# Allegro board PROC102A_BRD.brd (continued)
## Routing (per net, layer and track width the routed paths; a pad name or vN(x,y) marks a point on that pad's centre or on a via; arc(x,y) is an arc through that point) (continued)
N171944000: length 1.5
  BOTTOM w0.152: R91.1 103.4,88.17 Q9.2
N171947950: length 1.5
  BOTTOM w0.152: R96.1 103.4,138.59 Q10.2
N171966200: length 1.5
  BOTTOM w0.152: Q11.2 103.4,113.06 R97.1

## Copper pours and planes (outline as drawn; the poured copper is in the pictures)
5VOP on TOP: 108.27,28.57 108.27,24.7 111.36,24.7 111.36,28.57
5VOP on BOTTOM: 100.02,29.26 100.02,20.22 103.71,20.22 103.71,25.74 111.26,25.74 111.26,29.26
DGND on TOP: 23.64,1.03 23.64,25.48 8.14,25.48 8.14,152.56 150.28,152.56 151.29,152.56 151.29,26.42 151.3,26.42 151.3,25.46 135.76,25.46 135.76,9.82 135.05,9.11 135.05,9.29 128.7,2.93 97.78,2.93 97.78,1.03 ; 48 cut-outs
DGND on TOP: 71.12,125.05 71.12,119.82 66,119.82 66,125.05
DGND on TOP: 105.68,28.77 105.68,32.71 100.97,32.71 100.97,28.77
DGND on TOP: 70.23,127.76 70.23,134.61 65.88,134.61 65.88,127.76
DGND on TOP: 71.02,112.31 71.02,117.58 65.9,117.58 65.9,112.31
DGND on L02_GND1: 23.62,1.02 23.63,25.47 8.13,25.47 8.13,152.57 151.29,152.57 151.3,128.96 151.3,25.88 151.3,25.46 135.76,25.46 135.76,9.82 134.87,8.93 134.87,9.05 128.9,3.08 97.86,3.08 97.71,2.93 97.71,1.02
DGND on L05_GND2: 23.71,1.02 23.71,25.47 8.13,25.47 8.13,152.57 151.29,152.57 151.3,128.96 151.3,25.78 151.3,25.46 135.76,25.46 135.76,9.82 135.05,9.11 135.05,9.36 128.73,3.03 97.66,3.03 97.64,3.01 97.64,1.02
VCC1V8_HSE on BOTTOM: 70.08,1.81 83.33,1.81 83.33,3.34 78.49,3.34 78.49,4.3 71.47,4.3 71.47,4.53 66.7,4.53 66.7,3.52 70.08,3.52
VCC1V8_HSE on L04_PWR: 80.39,2.75 80.39,16 91.23,16 91.23,38.31 67,38.31 67,87.42 77.18,87.42 77.6,87 77.6,85.34 75.69,83.44 74.99,83.44 74.99,44.77 82.31,44.77 82.31,45.56 96.3,45.56 96.3,13.15 85.56,13.15 85.56,2.75
VCC3V3_IO_HSE on TOP: 86.58,129.98 86.58,126.14 84.52,126.14 84.52,124.55 84.02,124.55 84.02,129.98
VCC3V3_IO_HSE on TOP: 29.31,5.08 29.31,1.08 36.22,1.08 36.22,2.25 30.87,2.25 30.87,5.08
VCC3V3_IO_HSE on L04_PWR: 23.62,1.02 23.63,25.47 8.13,25.47 8.13,152.57 151.29,152.57 151.3,128.96 151.3,25.88 151.3,25.46 135.76,25.46 135.76,11.68 135.36,11.68 135.36,11 135.78,11 135.78,9.96 128.82,3 97.79,3 97.72,2.93 97.72,1.02 ; 6 cut-outs
VCC_5V0_HSE on TOP: 76.54,1.04 76.54,1.93 67.09,1.93 67.09,1.04
VCC_5V0_HSE on L04_PWR: 72.49,2.25 72.49,1.03 93.54,1.03 93.54,8.82 101.87,8.82 101.87,25.08 111.89,25.08 111.89,31.32 103.51,31.32 103.51,49.66 102.73,50.43 89.56,50.43 89.56,87.93 80.66,87.93 80.66,75.33 80.84,75.33 80.84,46.14 96.56,46.14 96.56,11.77 86.77,11.77 86.77,2.25
VCC_24V0 on BOTTOM (solid shape): 117.58,139.34 112.25,139.34 112.25,140.1 111.72,140.1 111.72,140.2 110.7,140.2 110.7,140.49 111.72,140.49 111.72,140.52 111.76,140.52 112.1,140.85 117.58,140.85
VCC_24V0 on BOTTOM (solid shape): 117.58,113.81 112.25,113.81 112.25,114.57 111.72,114.57 111.72,114.68 110.7,114.68 110.7,114.97 111.72,114.97 111.72,114.99 111.76,114.99 111.99,115.22 117.58,115.22
VCC_24V0 on BOTTOM (solid shape): 117.58,63.01 112.25,63.01 112.25,63.77 111.72,63.77 111.72,63.88 110.7,63.88 110.7,64.17 111.72,64.17 111.72,64.19 111.76,64.19 111.99,64.42 117.58,64.42
VCC_24V0 on BOTTOM (solid shape): 142.85,114.2 137.52,114.2 137.52,114.95 136.99,114.95 136.99,115.06 135.97,115.06 135.97,115.35 136.99,115.35 136.99,115.37 137.04,115.37 137.26,115.6 142.85,115.6
VCC_24V0 on BOTTOM (solid shape): 142.85,88.8 137.52,88.8 137.52,89.55 136.99,89.55 136.99,89.66 135.97,89.66 135.97,89.95 136.99,89.95 136.99,89.97 137.04,89.97 137.31,90.24 142.85,90.24
VCC_24V0 on BOTTOM (solid shape): 142.96,139.65 137.63,139.65 137.63,140.41 137.11,140.41 137.11,140.52 136.09,140.52 136.09,140.8 137.11,140.8 137.11,140.83 137.15,140.83 137.38,141.06 142.96,141.06
VCC_24V0 on BOTTOM (solid shape): 142.98,63.01 137.65,63.01 137.65,63.77 137.12,63.77 137.12,63.88 136.1,63.88 136.1,64.17 137.12,64.17 137.12,64.19 137.16,64.19 137.39,64.42 142.98,64.42
VCC_24V0 on BOTTOM (solid shape): 117.58,88.92 112.25,88.92 112.25,89.68 111.72,89.68 111.72,89.78 110.7,89.78 110.7,90.07 111.72,90.07 111.72,90.1 111.76,90.1 112.1,90.44 114.81,90.44 114.86,90.44 114.91,90.46 117.58,90.46
VCC_24V0 on TOP: 85.87,104.41 83.55,104.41 83.55,107.59 71.42,107.59 71.42,104.46 68.91,104.46 68.91,113.71 73,113.71 73,114.89 72.99,114.89 72.99,126.59 80.66,126.59 80.66,122.54 85.87,122.54 85.87,122.56 92.44,122.56 92.44,145.66 143.87,145.66 143.87,143.89 94.62,143.89 94.62,119.89 85.87,119.89
VCC_24V0 on TOP: 123.87,29.1 123.87,31.75 121.16,31.75 121.16,29.1
VCC_24V0 on L03_SIG1: 140.97,66 140.97,62.36 140.97,62.36 140.97,33.78 120.86,33.78 120.86,27.81 144.4,27.81 144.4,66
VCC_24V0 on L03_SIG1: 116.21,139.06 124.84,139.06 124.84,143 140.08,143 140.08,139.19 143.89,139.19 143.89,147.2 116.21,147.2
VCC_24V0 on L04_PWR: 120.52,32 125.73,32 125.73,14.66 127.39,13 135.64,13 135.64,9.88 132.86,7.11 125.1,7.11 120.52,11.68
(no net) on BOTTOM: 112.25,63.01 112.25,63.77 110.67,63.77 110.67,64.42 117.58,64.42 117.58,63.01
(no net) on BOTTOM: 112.25,113.81 112.25,114.57 110.67,114.57 110.67,115.22 117.58,115.22 117.58,113.81
(no net) on BOTTOM: 137.52,114.2 137.52,114.95 135.94,114.95 135.94,115.6 142.85,115.6 142.85,114.2
(no net) on BOTTOM: 112.25,88.92 112.25,89.68 110.67,89.68 110.67,90.46 117.58,90.46 117.58,88.92
(no net) on BOTTOM: 137.52,88.8 137.52,89.55 135.94,89.55 135.94,90.24 142.85,90.24 142.85,88.8
(no net) on BOTTOM: 112.25,139.34 112.25,140.1 110.67,140.1 110.67,140.85 117.58,140.85 117.58,139.34
(no net) on BOTTOM: 137.63,139.65 137.63,140.41 136.06,140.41 136.06,141.06 142.96,141.06 142.96,139.65
(no net) on BOTTOM: 137.65,63.01 137.65,63.77 136.07,63.77 136.07,64.42 142.98,64.42 142.98,63.01
(no net) on BOTTOM: 23.64,1.03 23.64,25.48 8.14,25.48 8.14,152.56 150.28,152.56 151.29,152.56 151.29,25.47 135.75,25.47 135.75,9.93 128.75,2.93 97.78,2.93 97.78,1.03 ; 61 cut-outs
(no net) on L03_SIG1: 23.62,1.02 23.63,25.47 8.13,25.47 8.13,152.57 151.29,152.57 151.3,128.96 151.3,25.83 151.3,25.46 135.76,25.46 135.76,9.82 135.1,9.16 135.1,9.28 128.9,3.08 97.82,3.08 97.79,3.05 97.79,1.14 97.66,1.02 ; 58 cut-outs
INPUT_24V0 on TOP: 70.97,139.57 70.97,127.9 80.55,127.9 80.55,139.57
L+_1 on TOP: 72.31,104.5 72.31,106.09 72.08,106.09 72.08,111.57 73.51,111.57 73.51,107.92 73.36,107.92 73.36,104.5
L+_1 on L04_PWR: 73.33,107.86 70.85,107.86 70.85,144.7 128.91,144.7 128.91,133.46 133.99,133.46 133.99,129.83 124.51,129.83 124.51,140.79 73.33,140.79
L+_2 on TOP: 73.56,104.5 73.56,106.23 79.76,106.23 79.76,104.5
L+_2 on L04_PWR: 77.92,106.47 77.92,104.54 80.77,104.54 80.77,120.52 121.69,120.52 121.69,105.28 134.09,105.28 134.09,109.73 127.26,109.73 127.26,125.1 78.74,125.1 78.74,106.47
L+_3 on TOP: 68.1,104.5 68.1,106.96 68.09,106.96 68.09,107.96 64.22,107.96 64.22,106.71 67.05,106.71 67.05,104.5
L+_3 on L04_PWR: 63.87,106.63 63.87,108.36 69.18,108.36 70.55,107 73.45,107 77.09,103.36 77.09,96.77 93.96,96.77 98.5,92.24 98.5,76.58 130.36,76.58 130.36,82.6 134.56,82.6 134.56,73.41 95.96,73.41 95.96,91.72 93.07,94.62 76.84,94.62 75.06,96.39 75.06,103.12 73.61,104.57 68.91,104.57 66.85,106.63
L+_4 on TOP: 66.85,104.5 66.85,106.07 63.3,106.07 63.3,104.5
L+_4 on L04_PWR: 62.95,106.11 62.95,93.01 66.93,89.03 90.68,89.03 90.68,52.38 102.03,52.38 105.52,48.89 135.09,48.89 135.09,57.78 130.84,57.78 130.84,51.9 106.85,51.9 104.02,54.74 93.03,54.74 93.03,90.74 92.04,91.73 68.8,91.73 65.53,95 65.53,106.11
L+_5 on TOP: 86.89,104.5 86.89,106.96 86.89,106.96 86.89,110.62 90.73,110.62 90.73,107.28 87.93,107.28 87.93,104.5
L+_5 on L04_PWR: 86.54,110.52 86.54,108.46 96.9,108.46 107.38,97.98 132.65,97.98 140.97,89.66 140.97,70.06 113.16,70.06 113.16,57.61 106.05,57.61 106.05,55.63 108.17,53.5 117.76,53.5 117.76,66.35 145.16,66.35 145.16,92.2 136.02,101.35 107.32,101.35 98.15,110.52
L+_6 on TOP: 88.13,104.5 88.13,106.5 94.36,106.5 94.36,101.41 91.74,101.41 91.74,104.5
L+_6 on L04_PWR: 91.63,103.44 91.63,101.09 94.87,101.09 101.47,94.49 101.47,79.5 108.64,79.5 108.64,83.14 104.25,83.14 104.25,95.87 96.68,103.44
L+_7 on TOP: 82.67,104.5 82.67,106.96 82.66,106.96 82.66,111.91 81.49,111.91 81.49,106.36 81.86,106.36 81.86,104.5
L+_7 on L04_PWR: 81.61,106.38 81.61,120.02 115.95,120.02 115.95,104.64 107.71,104.64 106.3,106.05 106.3,107.82 113.31,107.82 113.31,115.44 83.82,115.44 83.82,106.38
L+_8 on TOP: 81.42,104.5 81.42,105.95 81.03,105.95 81.03,109.86 76.07,109.86 76.07,106.93 80.12,106.93 80.12,104.5
L+_8 on L04_PWR: 76.09,107.58 78.06,107.58 78.06,130.64 108.84,130.64 108.84,134.09 76.09,134.09
N16732073 on TOP: 115.26,24.59 115.26,28.14 123.26,28.14 123.26,24.59
N16811368 on TOP: 91.63,134.04 91.63,143.35 82.32,143.35 82.32,134.04

Small or netless copper shapes (teardrops, artwork), in the pictures only: 259 on TOP, 313 on BOTTOM, 168 on L03_SIG1

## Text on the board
Ref Des/Assembly Bottom: PROC102A  ASSEMBLY BOTTOM
User.Comments: 5 | 6 | B1 | 2 | A14 | A2 | B2 | 4 | A10 | B10 | 11 | 8 | A12 | B12 | 12 | 16 | 30 | 37 | A32 | B32 | 24 | 25 | 36 | A31 | 9 | 10 | 13 | 18 | 19 | 20 | C | B | A | E | D | 3 | 7 | 15 | 32 | 33 | 31 | 64 | 65 | 96 | 40 | 23 | A11 | B11 | B14 | 48 | 128 | 21 | 97 | R170 | FSI | J23 | J24 | R8 | LD10 | J7 | C1 | J10 | R2 | TP28 | CPSW PHY | R3 | L7 | C23 | C143 | MCAN1 | R99 | LD25 | FB1 | TP5 | J14 | R153 | C122 | U32 | C2 | FB2 | R4 | R5 | C24 | MCAN0 | U36 | J27 | J9 | J31 | J21 | C28 | LD1 | R110 | R102 | C73 | C80 | C76 | C39 | C38 | C43 | R70 | TP11 | U9 | TP9 | C139 | C114 | R151 | C106 | TP19 | TP39 | R30 | U15 | C14 | FL7 | TP16 | C101 | C99 | C90 | C147 | TP17 | C205 | TP6 | U34 | C16 | R135 | C184 | R126 | R128 | L1 | C110 | C104 | R23 | TP56 | R52 | R56 | LD17 | C78 | C83 | C44 | C41 | U27 | U49 | R107 | R108 | R16 | TP96 | C89 | R51 | R54 | TP31 | C26 | J30 | J2 | R201 | R53 | R45 | R40 | U8 | HSE | C34 | C161 | J25 | RA2 | RA1 | U51 | TP43 | TP40 | C181 | R150 | R50 | R55 | R185 | TP20 | R19 | C100 | C102 | R93 | R98 | C168 | R189 | TP21 | C144 | R72 | R68 | TP7 | R177 | RA4 | R29 | C169 | R190 | C15 | U37 | R22 | R46 | BOOTMODE 0-7 | C121 | J8 | SW2 | C155 | C162 | U46 | R167 | U1 | R148 | U13 | R176 | R168 | TP4 | C476 | U23 | C145 | C146 | R157 | TP30 | U45 | R138 | R137 | TP15 | C133 | L2 | U48 | TP42 | C9 | R38 | C64 | R69 | R71 | R77 | SW3 | VDD CORE | U40 | C4 | U60 | GND | C134 | JTAG MUX SEL | Y1 | R140 | C27 | BOOTMODE 8-15 | R156 | R158 | R173 | R169 | R172 | C148 | C86 | J5 | TP54 | R174 | TP55 | C79 | C477 | C479 | I2C0 | U39 | J3 | SW4 | C113 | MCU PORz | ADC | VDDR CORE | C173 | R15 | U57 | R106 | R78 | C22 | C7 | R73 | SW5 | C45 | MCU RST | J20 | TP46 | TP23 | SOC WARM RST | R43 | U50 | U44 | TP70 | TP29 | C30 | R574 | U10 | C47 | R24 | R13 | J22 | J13 | C117 | SW6 | R191 | R92 | C72 | C486 | C77 | R12 | R192 | R186 | LD7 | C50 | C189 | U56 | TP24 | I2C1 | C171 | U33 | J4 | J19 | SW7 | J1 | R583 | R116 | R122 | LD20 | R143 | C57 | C54 | C174 | C176 | R82 | C151 | U11 | LD22 | R113 | R119 | TP32 | LD4 | C40 | C46 | U17 | U6 | L6 | C10 | C84 | C66 | C65 | R142 | TP12 | C167 | TP8 | R28 | J11 | C123 | L3 | U21 | U59 | R206 | TP2 | R207 | C31 | R20 | C33 | TP34 | R208 | D4 | C107 | C37 | TP38 | MCU RSTSTATz | LD15 | LD2 | U30 | C177 | C108 | 12V IN | C198 | U43 | LD5 | R204 | F1 | C56 | TP1 | D5 | R64 | J6 | R198 | R199 | C197 | R200 | U22 | C195 | C69 | OFF | C152 | C154 | U42 | Y2 | D6 | R7 | U58 | R134 | ON | FB8 | U61 | LD9 | C71 | D1 | C125 | D3 | R109 | R112 | TP18 | UART | TP81 | SW1 | JTAG | J28 | J26 | R80 | Q7 | Q4 | U19 | U31 | Q3 | U18 | U2 | U47 | U7 | U29 | U35 | Q1 | Q10 | Q8 | U41 | Q5 | Q2 | C153 | C29 | U3 | R136 | C3 | J32 | R9 | U4 | C140 | TP99 | C127 | C128 | C8 | C25 | ICSSG PHY | R76 | R37 | C141 | C111 | C67 | R564 | R565 | R94 | C112 | R96 | R97 | R95 | FB9 | C124 | R31 | R114 | R32 | LD11 | R115 | LD16 | R33 | R100 | R35 | U20 | R120 | R81 | R34 | R36 | R101 | R79 | C52 | R105 | LD12 | R42 | C51 | R104 | C36 | LD13 | C35 | R103 | C105 | LD18 | R41 | C68 | LD14 | R39 | LD19 | R121 | LD24 | LATCH IN1 | R59 | J15 | R60 | SYNC OUT2 | R61 | R21 | J16 | R65 | LATCH IN0 | J17 | SYNC OUT0 | TP22 | J18 | R187 | TP41 | RA3 | C58 | R83 | C18 | R194 | R84 | C91 | R85 | C182 | C92 | C59 | R86 | C93 | C19 | R188 | C11 | C60 | R87 | C12 | C61 | R88 | C53 | R195 | C13 | C62 | R89 | C183 | R90 | TP48 | C63 | R91 | R66 | R67 | C17 | R1 | C42 | R147 | R11 | C120 | R10 | FB6 | TP47 | LD26 | C156 | SOC/MCU GPIO | C163 | MCU WARM RST | U5 | R155 | SOC POR RST | R62 | C190 | R154 | R210 | R63 | R600 | C20 | R152 | R197 | C164 | R139 | C21 | C157 | R25 | LD23 | C165 | R178 | R179 | C75 | C387 | R180 | C98 | C194 | C103 | C74 | R181 | TP68 | RSTSTATz | J29 | FB5 | TP82 | R183 | FB3 | C97 | C87 | PORz OUT | R184 | R75 | R17 | R26 | R159 | R18 | R27 | R196 | C170 | R160 | R297 | R161 | R162 | TP61 | TP63 | R163 | SYNC1 OUT | C482 | C150 | C179 | R164 | R193 | U103 | C149 | J12 | LD3 | R124 | R165 | R132 | R166 | R125 | C483 | TP33 | R133 | C484 | L4 | TP14 | R575 | C495 | TP25 | TP27 | C485 | R14 | U14 | R74 | R144 | C95 | C178 | R145 | R127 | C494 | U102 | R123 | R175 | U25 | C129 | U16 | C109 | R47 | R117 | R584 | LD21 | R118 | R48 | TP51 | SAFETY | C96 | C126 | TP52 | C32 | R579 | C55 | C188 | U55 | LD8 | U28 | C5 | R602 | C70 | C180 | C6 | TP44 | C48 | C192 | R171 | TP26 | C49 | TP10 | C166 | R131 | R202 | C94 | R203 | C118 | C196 | U12 | R205 | C135 | TP3 | R57 | C136 | R130 | R58 | R578 | TP37 | C131 | C115 | C137 | TP35 | C138 | C81 | U24 | TP36 | R209 | D2 | C175 | U26 | C172 | C193 | C158 | R577 | C82 | ON/OFF SWITCH | C132 | C116 | C159 | R141 | R6 | L5 | R129 | C191 | C185 | C160 | C85 | C186 | C130 | R182 | C187 | LD6 | R111 | U52 | U53 | U104 | U54 | Q9 | Q6 | BOARD NAME: | IO Link/Breakout Board | REV: A | DATE: 22/09/2020 | DESCRIPTION: | SHEET | OF | SCALE: 1 | DISPLAY | PCIE | ASSY# | SL# | TMDS64GPEVM | PROC101E2 | AM64x EVM | USB2.0 | TEXAS INSTRUMENTS
Ref Des/Assembly Top: PROC102A  ASSEMBLY TOP
Ref Des/Silkscreen Top: For Evaluation Only, Not FCC Approved for Resale | OPN# | IO Link/Breakout Board | PROC102A | REV. A | ASSY#
PAGE_OUTLINE: LAYOUT BY | REVIEWED BY | APPROVED BY | SIGNATURES | AMB | VU | ZA | 221020 | DATE | SIZE | SCALE: | D | NONE | SHEET 1 OF 13 | PROC102 | Rev | A | TEXAS INSTRUMENTS | IO Link/Breakout Board
DIMENSION: 16. ENSURE THAT UL REGISTERED E-FILE NUMBER IS ON THE PCB SILKSCREEN
User.12: A | B | C | D | E | 1 | 30
User.14: 30 | C | B | A | E | D | 20 | 19 | 2 | HSE | I2C0 | ADC | I2C1 | 3
User.16: 5 | 6 | B1 | 2 | A14 | A2 | B2 | 4 | A10 | B10 | 11 | 8 | A12 | B12 | 12 | 16 | 30 | 37 | A32 | B32 | 24 | 25 | 36 | A31 | 9 | 10 | 13 | 18 | 19 | 20 | C | B | A | E | D | 3 | 7 | 15 | 32 | 33 | 31 | 64 | 65 | 96 | 40 | 23 | A11 | B11 | B14 | 48 | 128 | 21 | 97 | FSI | DISPLAY | CPSW PHY | MCAN1 | MCAN0 | PCIE | ASSY# | HSE | SL# | BOOTMODE 0-7 | VDD CORE | GND | JTAG MUX SEL | BOOTMODE 8-15 | TMDS64GPEVM | PROC101E2 | AM64x EVM | I2C0 | MCU PORz | ADC | VDDR CORE | MCU RST | SOC WARM RST | I2C1 | SAFETY | MCU RSTSTATz | 12V IN | OFF | ON | UART | JTAG | USB2.0 | ICSSG PHY | LATCH IN1 | SYNC OUT2 | LATCH IN0 | SYNC OUT0 | SOC/MCU GPIO | MCU WARM RST | SOC POR RST | RSTSTATz | PORz OUT | SYNC1 OUT | ON/OFF SWITCH | R | TITLE: | PROC101E2 AM64x EVM BOARD | #60, ADARSH REGENT, 100'FT RING ROAD, | DOMLUR EXTENSION, BANGALORE-560 071 | SHEET    OF 17 | DATE: | 04SEP20 | REV | E2 | SCALE: 1 | MISTRAL | PROC101E2 ASSEMBLY TOP REV E2 | MISTRAL SOLUTIONS PVT.LTD.,
User.45: TOP ASSEMBLY V1 | TOP ASSEMBLY V2 | 01 | 02 | BOTTOM ASSEMBLY V2 | FIGURE | SIZE | 8.0 | 30.0 | 40.0 | 44.0 | 48.0 | 32.0 | 50.0 | 108.0 | 80.0x40.0 | DRILL CHART: TOP to BOTTOM | ALL UNITS ARE IN MILS | TOLERANCE | +3.0/-3.0 | +2.0/-2.0 | PLATED | NON-PLATED | QTY | 834 | 20 | 6 | 605 | 3 | 40 | 24 | 2 | 16 | 1 | REV # | SCALE:NONE | FILE NAME: | DESCRIPTION | REVISIONS | CCN # | DRAWING NO. | DDMMYY | DATE | OF | REV | SHEET | 6 - Provide serial numbers to the assembled boards for identification. | 7 - The assembled board are wrapped in ESD Covers(individual) and packed securely before shipment. | ASSEMBLY NOTES:- | 1 - All MSL components should be baked as per JEDEC standard. | 2 - PCB should be baked at 120 degree for 8 hours. | 3 - Board assembly must comply with workmanship standards IPC-A-610 Class 2, unless otherwise specified. | 4 - These assemblies are ESD sensitive, ESD precautions shall be observed. | 5 - These assemblies must be clean and free from flux and all contaminants. Use of no clean flux is not acceptable. | PROC102 A (002) ASSEMBLY TOP | PROC102 A (002)  ASSEMBLY BOTTOM | C | FY10XXXX5200X0X | *
